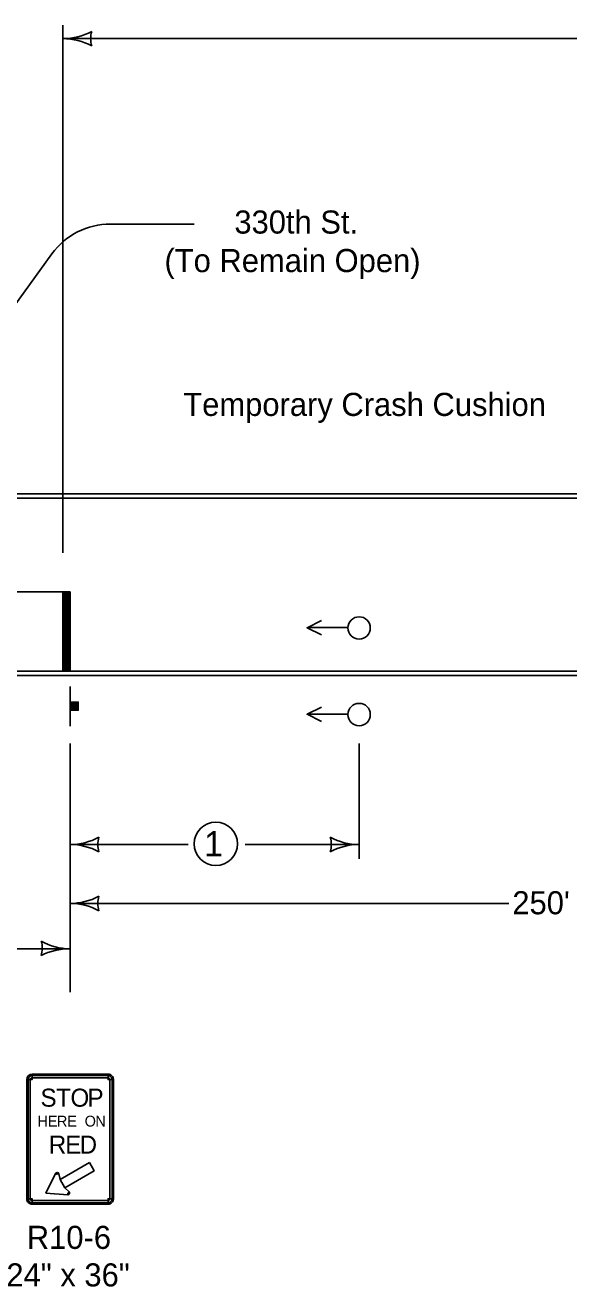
# Model space of a CAD drawing. Extents: x 10124 to 16850, y 7924 to 12166.
# Drawn here: x 14343 to 14719, y 8878 to 9752 of the extents above; entities that cross this region are included whole.
import ezdxf

# ---------------------------------------------------------------- set-up
doc = ezdxf.new("R2010")
doc.units = 0
for name, color, linetype in [('dsnCellElements', 7, 'Continuous'), ('dsnStdLabel', 7, 'Continuous'), ('dsnStdLineWork', 7, 'Continuous'), ('Level 2', 7, 'Continuous')]:
    doc.layers.add(name, color=color, linetype=linetype)

msp = doc.modelspace()

# ---------------------------------------------------------------- linework, layer by layer
at = {"layer": 'dsnCellElements'}
for centre, radius, start, end in [((14369.28, 9785.46), 42.5, 270, 298.07249), ((14369.28, 9700.46), 42.5, 61.92751, 90), ((14404.91, 9742.96), 16.42, 162.26665, 197.73335), ((14374.28, 9186.46), 42.5, 270, 298.07249), ((14409.91, 9143.96), 16.42, 162.26665, 197.73335), ((14374.28, 9101.46), 42.5, 61.92751, 90)]:
    msp.add_arc(centre, radius, start, end, dxfattribs=at)
at = {"layer": 'dsnStdLabel'}
for p, q in [((14344.28, 9021.94), (14348.03, 9021.94)), ((14345.21, 9021.94), (14346.78, 9021.94)), ((14348.03, 9021.94), (14348.03, 9025.69)), ((14348.03, 9023.19), (14348.03, 9024.75)), ((14400.53, 9025.69), (14400.53, 9021.94)), ((14400.53, 9024.75), (14400.53, 9023.19)), ((14400.53, 9021.94), (14404.28, 9021.94)), ((14401.78, 9021.94), (14403.34, 9021.94)), ((14364.13, 8956.96), (14365.24, 8956.38)), ((14365.24, 8956.38), (14366.46, 8956.65)), ((14348.03, 8939.44), (14344.28, 8939.44)), ((14346.78, 8939.44), (14345.21, 8939.44)), ((14348.03, 8935.69), (14348.03, 8939.44)), ((14372.74, 8943.39), (14372.69, 8942.14)), ((14373.59, 8944.31), (14372.74, 8943.39)), ((14404.28, 8939.44), (14400.53, 8939.44)), ((14400.53, 8939.44), (14400.53, 8935.69)), ((14403.34, 8939.44), (14401.78, 8939.44)), ((14348.03, 8936.63), (14348.03, 8938.19)), ((14400.53, 8938.19), (14400.53, 8936.63))]:
    msp.add_line(p, q, dxfattribs=at)
for points in [[(14348.03, 8935.69), (14400.53, 8935.69), (14400.53, 8939.44), (14404.28, 8939.44), (14404.28, 9021.94), (14400.53, 9021.94), (14400.53, 9025.69), (14348.03, 9025.69), (14348.03, 9021.94), (14344.28, 9021.94), (14344.28, 8939.44), (14348.03, 8939.44), (14348.03, 8935.69)], [(14346.78, 9021.94), (14346.78, 8939.44), (14345.21, 8939.44), (14345.21, 9021.94), (14346.78, 9021.94)], [(14400.53, 9023.19), (14348.03, 9023.19), (14348.03, 9024.75), (14400.53, 9024.75), (14400.53, 9023.19)], [(14401.78, 8939.44), (14401.78, 9021.94), (14403.34, 9021.94), (14403.34, 8939.44), (14401.78, 8939.44)], [(14357.62, 8943.32), (14372.69, 8942.14), (14372.74, 8943.39), (14373.59, 8944.31), (14370.62, 8947.03), (14367.34, 8952.72), (14366.46, 8956.65), (14365.24, 8956.38), (14364.13, 8956.96), (14357.62, 8943.32)], [(14387.65, 8964.44), (14390.93, 8958.76), (14370.62, 8947.03), (14367.34, 8952.72), (14387.65, 8964.44)], [(14348.03, 8938.19), (14400.53, 8938.19), (14400.53, 8936.63), (14348.03, 8936.63), (14348.03, 8938.19)]]:
    msp.add_lwpolyline(points, close=True, dxfattribs=at)
for centre, radius, start, end in [((14348.03, 9021.94), 3.75, 90.00021, 179.99985), ((14348.03, 9021.94), 2.81, 90.00021, 179.99985), ((14348.03, 9021.94), 1.25, 90.00021, 179.99985), ((14400.53, 9021.94), 3.75, 0, 90.00021), ((14400.53, 9021.94), 2.81, 0, 90.00021), ((14400.53, 9021.94), 1.25, 0, 90.00021), ((14365.24, 8956.38), 1.25, 12.62232, 152.27557), ((14348.03, 8939.44), 3.75, 179.99985, 270.00006), ((14348.03, 8939.44), 2.81, 179.99985, 270.00006), ((14348.03, 8939.44), 1.25, 179.99985, 270.00006), ((14372.74, 8943.39), 1.25, 267.72427, 47.37758), ((14400.53, 8939.44), 3.75, 270.00006, 0.00027), ((14400.53, 8939.44), 2.81, 270.00006, 0.00027), ((14400.53, 8939.44), 1.25, 270.00006, 0.00027)]:
    msp.add_arc(centre, radius, start, end, dxfattribs=at)
at = {"layer": 'dsnStdLineWork'}
for p, q in [((14322.86, 9424.79), (14369.28, 9424.79)), ((14369.28, 9427.79), (14324.05, 9427.79)), ((14842.25, 9427.79), (14369.28, 9427.79)), ((14369.28, 9427.79), (14369.28, 9424.79)), ((14369.28, 9424.79), (14369.28, 9427.79)), ((14369.28, 9424.79), (14844.42, 9424.79)), ((14374.28, 9359.79), (13924.28, 9359.79)), ((13724.28, 9304.79), (15224.27, 9304.79)), ((13724.28, 9304.79), (15224.27, 9304.79)), ((14369.28, 9304.79), (13724.28, 9304.79)), ((13724.28, 9301.79), (15224.27, 9301.79)), ((13724.28, 9301.79), (15224.27, 9301.79)), ((14370.28, 9304.79), (14369.28, 9304.79)), ((14371.28, 9304.79), (14370.28, 9304.79)), ((14372.28, 9304.79), (14371.28, 9304.79)), ((15224.27, 9304.79), (14374.28, 9304.79))]:
    msp.add_line(p, q, dxfattribs=at)
for points in [[(13723.86, 9424.79), (15033.86, 9424.79)], [(13724.28, 9427.79), (15034.28, 9427.79)], [(13724.28, 9424.79), (15034.28, 9424.79)], [(14374.28, 9304.79), (14373.28, 9304.79), (14372.28, 9304.79)]]:
    msp.add_lwpolyline(points, dxfattribs=at)
at = {"layer": 'Level 2'}
for p, q in [((14369.28, 9386.71), (14369.28, 9752.26)), ((14369.28, 9742.96), (15028.7, 9742.96)), ((14402.29, 9614.58), (14460.07, 9614.58)), ((14309.54, 9521.63), (14361.76, 9593.87)), ((15034.28, 9424.79), (13724.28, 9424.79)), ((14369.28, 9304.79), (14369.28, 9359.79)), ((14370.28, 9304.79), (14370.28, 9359.79)), ((14371.28, 9304.79), (14371.28, 9359.79)), ((14372.28, 9304.79), (14372.28, 9359.79)), ((14373.28, 9304.79), (14373.28, 9359.79)), ((14374.28, 9304.79), (14374.28, 9359.79)), ((14566.54, 9335.15), (14538.6, 9335.15)), ((13724.28, 9304.79), (15224.27, 9304.79)), ((14374.28, 9294.29), (14374.28, 9266.79)), ((14374.69, 9277.84), (14374.69, 9283.42)), ((14374.97, 9283.42), (14374.97, 9277.84)), ((14375.23, 9277.84), (14375.23, 9283.42)), ((14375.5, 9283.42), (14375.5, 9277.84)), ((14375.72, 9277.84), (14375.72, 9283.42)), ((14375.93, 9283.42), (14375.93, 9277.84)), ((14376.26, 9277.84), (14376.26, 9283.42)), ((14376.53, 9283.42), (14376.53, 9277.84)), ((14376.75, 9277.84), (14376.73, 9283.42)), ((14377.07, 9283.42), (14377.07, 9277.84)), ((14377.45, 9277.84), (14377.45, 9283.42)), ((14377.88, 9283.42), (14377.88, 9277.84)), ((14378.1, 9277.84), (14378.08, 9283.42)), ((14378.52, 9283.42), (14378.53, 9277.84)), ((14378.74, 9277.84), (14378.74, 9283.42)), ((14379.06, 9283.42), (14379.06, 9277.84)), ((14379.28, 9277.84), (14379.28, 9283.42)), ((14379.6, 9283.42), (14379.6, 9277.84)), ((14566.54, 9275.15), (14538.6, 9275.15)), ((14374.28, 9082.51), (14374.28, 9254.79)), ((14574.28, 9174.79), (14574.28, 9254.79)), ((14374.28, 9184.79), (14456.04, 9184.79)), ((14495.49, 9184.79), (14574.28, 9184.79)), ((14374.28, 9143.96), (14677.83, 9143.96)), ((14312.78, 9112.49), (14374.28, 9112.49))]:
    msp.add_line(p, q, dxfattribs=at)
for points in [[(14548.23, 9339.97), (14538.23, 9334.97), (14548.23, 9329.97)], [(14548.23, 9279.97), (14538.23, 9274.97), (14548.23, 9269.97)]]:
    msp.add_lwpolyline(points, dxfattribs=at)
msp.add_lwpolyline([(14374.37, 9277.84), (14374.37, 9283.46), (14380, 9283.46), (14380, 9277.84)], close=True, dxfattribs=at)
for centre, radius in [((14574.28, 9334.79), 7.74), ((14574.28, 9274.79), 7.74), ((14475.13, 9185.29), 15)]:
    msp.add_circle(centre, radius, dxfattribs=at)
for centre, radius, start, end in [((14402.29, 9564.58), 50, 90, 144.13795), ((14374.28, 9227.29), 42.5, 270, 298.07249), ((14374.28, 9142.29), 42.5, 61.92751, 90), ((14409.91, 9184.79), 16.42, 162.26665, 197.73335), ((14538.64, 9184.79), 16.42, 342.26665, 17.73335), ((14574.28, 9227.29), 42.5, 241.92751, 270), ((14574.28, 9142.29), 42.5, 90, 118.07249), ((14338.66, 9113.11), 16.42, 341.26665, 16.73335), ((14375.03, 9154.98), 42.5, 240.92751, 268.9824), ((14373.55, 9070), 42.5, 89.0176, 117.07249)]:
    msp.add_arc(centre, radius, start, end, dxfattribs=at)

# ---------------------------------------------------------------- texts
at = {"layer": 'dsnStdLabel'}
for s, height, p in [('S', 12.5, (14353.83, 9003.19)), ('T', 12.5, (14364.59, 9003.19)), ('O', 12.5, (14374.58, 9003.19)), ('P', 12.5, (14386.33, 9003.19)), ('H', 7.5, (14351.75, 8989.44)), ('E', 7.5, (14358.9, 8989.44)), ('R', 7.5, (14365.16, 8989.44)), ('E', 7.5, (14372.31, 8989.44)), ('O', 7.5, (14384.38, 8989.44)), ('N', 7.5, (14391.76, 8989.44)), ('R', 12.5, (14359.59, 8970.69)), ('E', 12.5, (14370.92, 8970.69)), ('D', 12.5, (14380.88, 8970.69))]:
    msp.add_text(s, height=height, dxfattribs=at).set_placement(p)
at = {"layer": 'Level 2'}
for s, height, p in [('330th St.', 16, (14487.96, 9607.94)), ('(To Remain Open)', 16, (14439.59, 9581.27)), ('Temporary Crash Cushion', 16, (14452.63, 9481.63)), ('1', 17.5, (14467.07, 9176.54)), ("250'", 16, (14680.28, 9136.46)), ('R10-6', 16, (14344.35, 8904.69)), ('24" x 36"', 16, (14330.21, 8878.69))]:
    msp.add_text(s, height=height, dxfattribs=at).set_placement(p)

doc.saveas('drawing.dxf')
